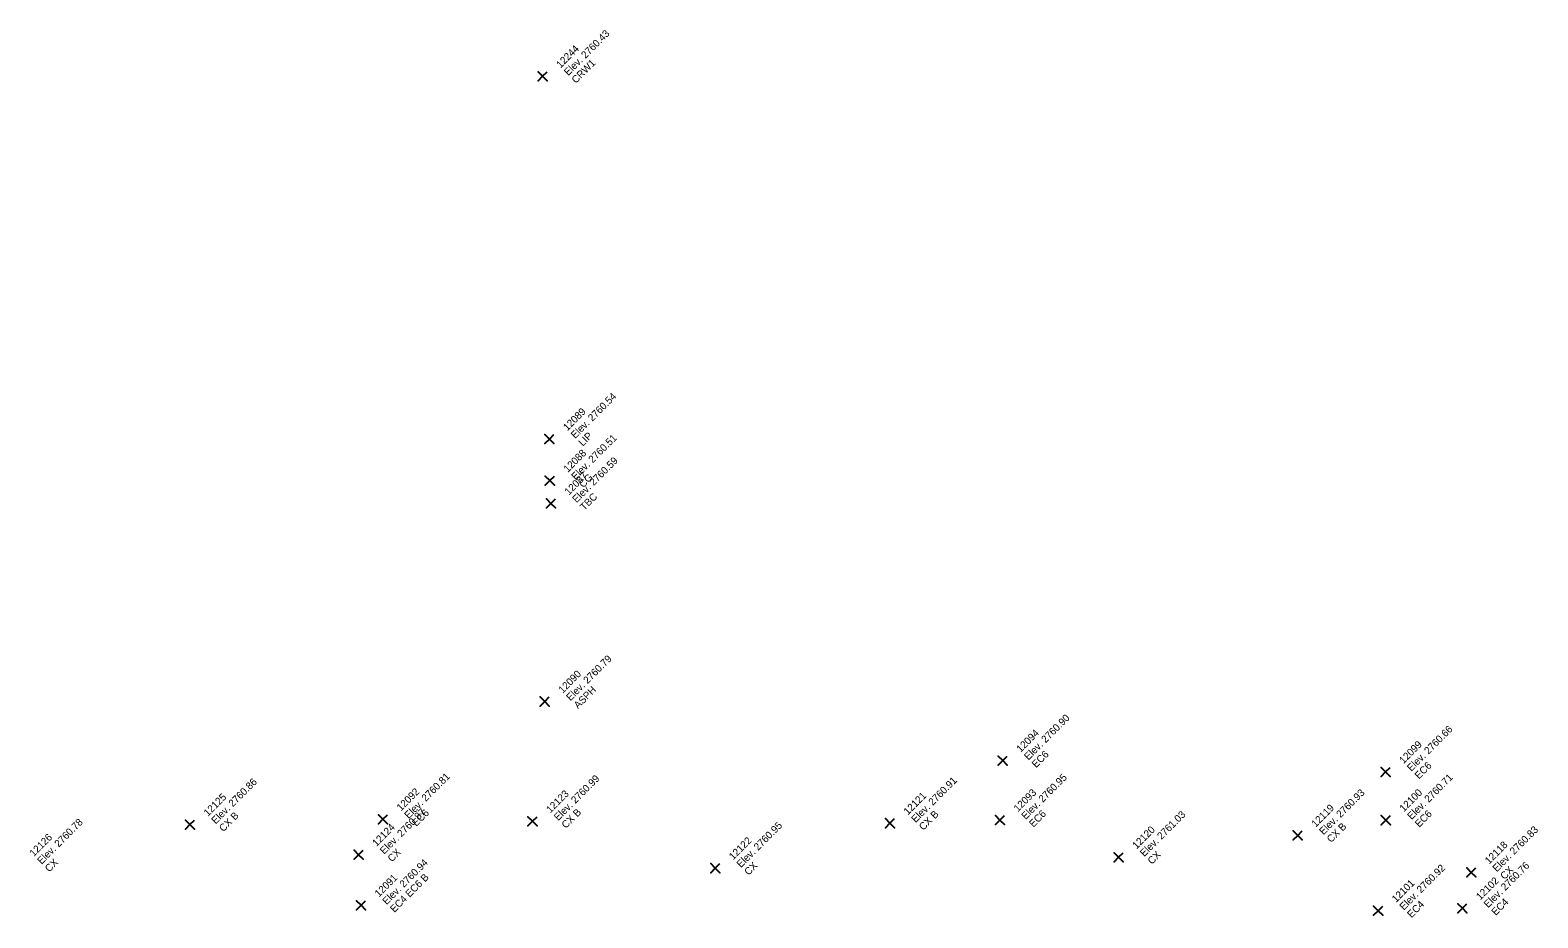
# Model space of a CAD drawing. Extents: x 2493999 to 2503109, y 700767 to 706646.
# Drawn here: x 2502360.09 to 2502409.94, y 702196.06 to 702225.39 of the extents above; entities that cross this region are included whole.
import ezdxf

# ---------------------------------------------------------------- set-up
doc = ezdxf.new("R2010")
doc.units = 0
doc.layers.add('ALG_CL_BLUE_Horiz', color=7, linetype='Continuous')
doc.layers.add('DES_SURFACE_Existing-Ground', color=7, linetype='Continuous')

msp = doc.modelspace()

# ---------------------------------------------------------------- linework, layer by layer
at = {"layer": 'ALG_CL_BLUE_Horiz'}
for points in [[(2502377.032, 702223.869), (2502376.882, 702224.019), (2502377.032, 702223.869), (2502376.882, 702223.719), (2502377.032, 702223.869), (2502377.182, 702223.719), (2502377.032, 702223.869), (2502377.182, 702224.019)], [(2502377.259, 702211.879), (2502377.109, 702212.029), (2502377.259, 702211.879), (2502377.109, 702211.729), (2502377.259, 702211.879), (2502377.409, 702211.729), (2502377.259, 702211.879), (2502377.409, 702212.029)], [(2502377.274, 702210.507), (2502377.124, 702210.657), (2502377.274, 702210.507), (2502377.124, 702210.357), (2502377.274, 702210.507), (2502377.424, 702210.357), (2502377.274, 702210.507), (2502377.424, 702210.657)], [(2502377.308, 702209.755), (2502377.158, 702209.905), (2502377.308, 702209.755), (2502377.158, 702209.605), (2502377.308, 702209.755), (2502377.458, 702209.605), (2502377.308, 702209.755), (2502377.458, 702209.905)], [(2502377.105, 702203.208), (2502376.955, 702203.358), (2502377.105, 702203.208), (2502376.955, 702203.058), (2502377.105, 702203.208), (2502377.255, 702203.058), (2502377.105, 702203.208), (2502377.255, 702203.358)], [(2502392.246, 702201.254), (2502392.096, 702201.404), (2502392.246, 702201.254), (2502392.096, 702201.104), (2502392.246, 702201.254), (2502392.396, 702201.104), (2502392.246, 702201.254), (2502392.396, 702201.404)], [(2502404.904, 702200.88), (2502404.754, 702201.03), (2502404.904, 702200.88), (2502404.754, 702200.73), (2502404.904, 702200.88), (2502405.054, 702200.73), (2502404.904, 702200.88), (2502405.054, 702201.03)], [(2502365.376, 702199.14), (2502365.226, 702199.29), (2502365.376, 702199.14), (2502365.226, 702198.99), (2502365.376, 702199.14), (2502365.526, 702198.99), (2502365.376, 702199.14), (2502365.526, 702199.29)], [(2502371.757, 702199.317), (2502371.607, 702199.467), (2502371.757, 702199.317), (2502371.607, 702199.167), (2502371.757, 702199.317), (2502371.907, 702199.167), (2502371.757, 702199.317), (2502371.907, 702199.467)], [(2502376.699, 702199.25), (2502376.549, 702199.4), (2502376.699, 702199.25), (2502376.549, 702199.1), (2502376.699, 702199.25), (2502376.849, 702199.1), (2502376.699, 702199.25), (2502376.849, 702199.4)], [(2502388.517, 702199.187), (2502388.367, 702199.337), (2502388.517, 702199.187), (2502388.367, 702199.037), (2502388.517, 702199.187), (2502388.667, 702199.037), (2502388.517, 702199.187), (2502388.667, 702199.337)], [(2502392.156, 702199.289), (2502392.006, 702199.439), (2502392.156, 702199.289), (2502392.006, 702199.139), (2502392.156, 702199.289), (2502392.306, 702199.139), (2502392.156, 702199.289), (2502392.306, 702199.439)], [(2502404.913, 702199.287), (2502404.763, 702199.437), (2502404.913, 702199.287), (2502404.763, 702199.137), (2502404.913, 702199.287), (2502405.063, 702199.137), (2502404.913, 702199.287), (2502405.063, 702199.437)], [(2502401.999, 702198.782), (2502401.849, 702198.932), (2502401.999, 702198.782), (2502401.849, 702198.632), (2502401.999, 702198.782), (2502402.149, 702198.632), (2502401.999, 702198.782), (2502402.149, 702198.932)], [(2502370.949, 702198.143), (2502370.799, 702198.293), (2502370.949, 702198.143), (2502370.799, 702197.993), (2502370.949, 702198.143), (2502371.099, 702197.993), (2502370.949, 702198.143), (2502371.099, 702198.293)], [(2502396.076, 702198.062), (2502395.926, 702198.212), (2502396.076, 702198.062), (2502395.926, 702197.912), (2502396.076, 702198.062), (2502396.226, 702197.912), (2502396.076, 702198.062), (2502396.226, 702198.212)], [(2502382.741, 702197.701), (2502382.591, 702197.851), (2502382.741, 702197.701), (2502382.591, 702197.551), (2502382.741, 702197.701), (2502382.891, 702197.551), (2502382.741, 702197.701), (2502382.891, 702197.851)], [(2502407.735, 702197.561), (2502407.585, 702197.711), (2502407.735, 702197.561), (2502407.585, 702197.411), (2502407.735, 702197.561), (2502407.885, 702197.411), (2502407.735, 702197.561), (2502407.885, 702197.711)], [(2502371.03, 702196.473), (2502370.88, 702196.623), (2502371.03, 702196.473), (2502370.88, 702196.323), (2502371.03, 702196.473), (2502371.18, 702196.323), (2502371.03, 702196.473), (2502371.18, 702196.623)], [(2502404.658, 702196.295), (2502404.508, 702196.445), (2502404.658, 702196.295), (2502404.508, 702196.145), (2502404.658, 702196.295), (2502404.808, 702196.145), (2502404.658, 702196.295), (2502404.808, 702196.445)], [(2502407.443, 702196.374), (2502407.293, 702196.524), (2502407.443, 702196.374), (2502407.293, 702196.224), (2502407.443, 702196.374), (2502407.593, 702196.224), (2502407.443, 702196.374), (2502407.593, 702196.524)]]:
    msp.add_lwpolyline(points, dxfattribs=at)

# ---------------------------------------------------------------- texts
at = {"layer": 'DES_SURFACE_Existing-Ground'}
for s, p in [('Elev. 2760.43', (2502377.881, 702223.869)), ('12244', (2502377.626, 702224.124)), ('CRW1', (2502378.135, 702223.614)), ('Elev. 2760.54', (2502378.108, 702211.879)), ('12089', (2502377.853, 702212.134)), ('LIP', (2502378.362, 702211.624)), ('12088', (2502377.868, 702210.762)), ('Elev. 2760.51', (2502378.123, 702210.507)), ('Elev. 2760.59', (2502378.157, 702209.755)), ('12087', (2502377.902, 702210.01)), ('CG', (2502378.377, 702210.252)), ('TBC', (2502378.411, 702209.5)), ('Elev. 2760.79', (2502377.954, 702203.208)), ('12090', (2502377.699, 702203.463)), ('ASPH', (2502378.208, 702202.953)), ('Elev. 2760.90', (2502393.095, 702201.254)), ('12094', (2502392.84, 702201.509)), ('Elev. 2760.66', (2502405.753, 702200.88)), ('EC6', (2502393.349, 702200.999)), ('12099', (2502405.498, 702201.135)), ('EC6', (2502406.007, 702200.625)), ('Elev. 2760.86', (2502366.225, 702199.14)), ('Elev. 2760.81', (2502372.606, 702199.317)), ('Elev. 2760.99', (2502377.548, 702199.25)), ('Elev. 2760.91', (2502389.366, 702199.187)), ('Elev. 2760.95', (2502393.005, 702199.289)), ('Elev. 2760.71', (2502405.762, 702199.287)), ('12125', (2502365.97, 702199.395)), ('12092', (2502372.351, 702199.572)), ('12123', (2502377.293, 702199.505)), ('12121', (2502389.111, 702199.442)), ('12093', (2502392.75, 702199.544)), ('Elev. 2760.93', (2502402.848, 702198.782)), ('12100', (2502405.507, 702199.542)), ('Elev. 2760.87', (2502371.798, 702198.143)), ('EC6', (2502372.86, 702199.062)), ('CX B', (2502377.802, 702198.995)), ('CX B', (2502389.62, 702198.932)), ('EC6', (2502393.259, 702199.034)), ('Elev. 2761.03', (2502396.925, 702198.062)), ('12119', (2502402.593, 702199.037)), ('EC6', (2502406.016, 702199.032)), ('Elev. 2760.78', (2502360.467, 702197.809)), ('CX B', (2502366.479, 702198.885)), ('12124', (2502371.543, 702198.398)), ('Elev. 2760.95', (2502383.59, 702197.701)), ('12120', (2502396.67, 702198.317)), ('CX B', (2502403.102, 702198.527)), ('Elev. 2760.83', (2502408.584, 702197.561)), ('12126', (2502360.212, 702198.064)), ('12122', (2502383.335, 702197.956)), ('12118', (2502408.329, 702197.816)), ('CX', (2502372.052, 702197.888)), ('CX', (2502397.179, 702197.807)), ('CX', (2502360.721, 702197.554)), ('Elev. 2760.94', (2502371.879, 702196.473)), ('CX', (2502383.844, 702197.446)), ('Elev. 2760.92', (2502405.507, 702196.295)), ('Elev. 2760.76', (2502408.292, 702196.374)), ('CX', (2502408.838, 702197.306)), ('12091', (2502371.624, 702196.728)), ('EC4 EC6 B', (2502372.133, 702196.218)), ('12101', (2502405.252, 702196.55)), ('12102', (2502408.037, 702196.629)), ('EC4', (2502405.761, 702196.04)), ('EC4', (2502408.546, 702196.119))]:
    msp.add_text(s, height=0.24, rotation=45, dxfattribs=at).set_placement(p)

doc.saveas('drawing.dxf')
